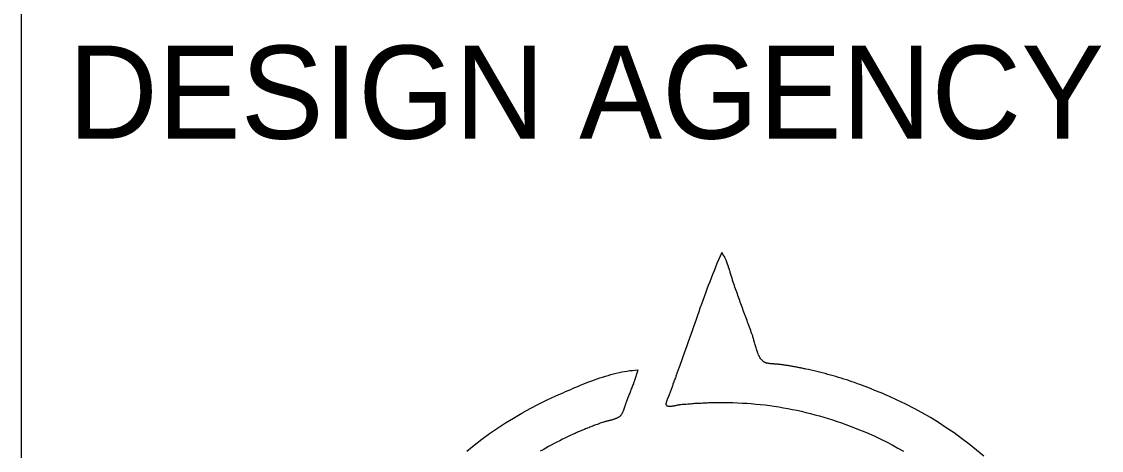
# Model space of a CAD drawing. Extents: x -0.7 to 34, y 0 to 22.
# Drawn here: x 32 to 33.162, y 4.015 to 4.476 of the extents above; entities that cross this region are included whole.
import ezdxf

# ---------------------------------------------------------------- set-up
doc = ezdxf.new("R2010")
doc.units = 0
doc.layers.add('SH_Border', color=7, linetype='Continuous')
doc.layers.add('SH_Text', color=7, linetype='Continuous')

msp = doc.modelspace()

# ---------------------------------------------------------------- linework, layer by layer
at = {"layer": 'SH_Border'}
msp.add_line((32, 0.5), (32, 21.5), dxfattribs=at)
at = {"layer": 'SH_Text'}
for points in [[(32.7532, 4.2277), (32.7515, 4.2238), (32.7498, 4.2199), (32.7481, 4.216), (32.7466, 4.212), (32.745, 4.208), (32.7434, 4.2041), (32.7418, 4.2001), (32.7403, 4.1961), (32.7387, 4.1921), (32.7372, 4.1881), (32.7357, 4.1841), (32.7342, 4.1801), (32.7328, 4.176), (32.7313, 4.172), (32.7298, 4.168), (32.7284, 4.1639), (32.7271, 4.1599), (32.7256, 4.1558), (32.7241, 4.1518), (32.7227, 4.1478), (32.7214, 4.1436), (32.7199, 4.1396), (32.7184, 4.1355), (32.7171, 4.1315), (32.7157, 4.1275), (32.7142, 4.1235), (32.7129, 4.1194), (32.7114, 4.1154), (32.71, 4.1114), (32.7085, 4.1074), (32.707, 4.1035)], [(32.7656, 4.1959), (32.7652, 4.1969), (32.7649, 4.1978), (32.7646, 4.1988), (32.7643, 4.1998), (32.764, 4.2009), (32.7637, 4.202), (32.7633, 4.2031), (32.7631, 4.2041), (32.7627, 4.2051), (32.7623, 4.2063), (32.7621, 4.2074), (32.7617, 4.2085), (32.7614, 4.2096), (32.761, 4.2107), (32.7606, 4.2118), (32.7603, 4.2129), (32.7599, 4.214), (32.7595, 4.2151), (32.7592, 4.2161), (32.7587, 4.2172), (32.7583, 4.2182), (32.7578, 4.2193), (32.7575, 4.2203), (32.757, 4.2214), (32.7565, 4.2223), (32.756, 4.2233), (32.7555, 4.2242), (32.7549, 4.2251), (32.7545, 4.226), (32.7538, 4.2268), (32.7532, 4.2277)], [(32.7856, 4.1404), (32.785, 4.1422), (32.7844, 4.144), (32.7837, 4.1457), (32.7831, 4.1475), (32.7823, 4.1493), (32.7817, 4.1512), (32.781, 4.1529), (32.7804, 4.1547), (32.7797, 4.1565), (32.7791, 4.1582), (32.7783, 4.16), (32.7777, 4.1618), (32.777, 4.1637), (32.7764, 4.1654), (32.7758, 4.1672), (32.7751, 4.169), (32.7745, 4.1708), (32.7739, 4.1725), (32.7731, 4.1743), (32.7725, 4.1761), (32.7719, 4.178), (32.7712, 4.1797), (32.7706, 4.1815), (32.77, 4.1833), (32.7694, 4.1851), (32.7686, 4.1869), (32.768, 4.1886), (32.7674, 4.1904), (32.7668, 4.1923), (32.7662, 4.1941), (32.7656, 4.1959)], [(32.7979, 4.1106), (32.7973, 4.1112), (32.7966, 4.1118), (32.796, 4.1124), (32.7954, 4.1131), (32.7949, 4.1138), (32.7943, 4.1147), (32.7939, 4.1156), (32.7934, 4.1165), (32.7929, 4.1175), (32.7925, 4.1186), (32.792, 4.1195), (32.7917, 4.1206), (32.7913, 4.1217), (32.7908, 4.1228), (32.7905, 4.1239), (32.7901, 4.1251), (32.7899, 4.1262), (32.7895, 4.1274), (32.7891, 4.1285), (32.7889, 4.1296), (32.7885, 4.1308), (32.7882, 4.1319), (32.7879, 4.133), (32.7877, 4.1341), (32.7873, 4.135), (32.7871, 4.136), (32.7868, 4.137), (32.7865, 4.138), (32.7862, 4.1388), (32.786, 4.1396), (32.7856, 4.1404)], [(32.5747, 4.0736), (32.5772, 4.0747), (32.5799, 4.0759), (32.5825, 4.077), (32.5852, 4.0782), (32.5879, 4.0794), (32.5907, 4.0806), (32.5934, 4.0818), (32.5962, 4.0829), (32.599, 4.0841), (32.6018, 4.0853), (32.6047, 4.0864), (32.6075, 4.0876), (32.6104, 4.0887), (32.6133, 4.0898), (32.6162, 4.0909), (32.6192, 4.0919), (32.6221, 4.093), (32.6251, 4.0938), (32.628, 4.0948), (32.6309, 4.0956), (32.6338, 4.0965), (32.6369, 4.0973), (32.6398, 4.0981), (32.6427, 4.0987), (32.6456, 4.0993), (32.6485, 4.0998), (32.6514, 4.1002), (32.6543, 4.1007), (32.6572, 4.101), (32.6601, 4.1012), (32.6629, 4.1015)], [(32.6629, 4.1015), (32.6626, 4.1002), (32.6623, 4.0992), (32.6619, 4.0979), (32.6616, 4.0969), (32.6612, 4.0958), (32.6609, 4.0945), (32.6605, 4.0935), (32.6601, 4.0922), (32.6596, 4.0912), (32.6593, 4.0901), (32.6589, 4.0888), (32.6584, 4.0878), (32.6581, 4.0867), (32.6576, 4.0856), (32.6572, 4.0844), (32.6567, 4.0833), (32.6564, 4.0822), (32.6559, 4.0811), (32.6555, 4.0799), (32.655, 4.0788), (32.6546, 4.0777), (32.6542, 4.0766), (32.6537, 4.0754), (32.6532, 4.0743), (32.6529, 4.0732), (32.6524, 4.0721), (32.652, 4.071), (32.6515, 4.0698), (32.6512, 4.0687), (32.6507, 4.0676), (32.6503, 4.0665)], [(32.707, 4.1035), (32.7067, 4.1025), (32.7063, 4.1016), (32.7061, 4.1006), (32.7057, 4.0996), (32.7054, 4.0987), (32.705, 4.0977), (32.7046, 4.0967), (32.7043, 4.0958), (32.7039, 4.0948), (32.7037, 4.0938), (32.7033, 4.0928), (32.7029, 4.092), (32.7026, 4.091), (32.7022, 4.0901), (32.7018, 4.0891), (32.7015, 4.0881), (32.7011, 4.0872), (32.7007, 4.0862), (32.7005, 4.0852), (32.7001, 4.0842), (32.6998, 4.0833), (32.6994, 4.0823), (32.699, 4.0813), (32.6987, 4.0804), (32.6983, 4.0795), (32.698, 4.0785), (32.6976, 4.0776), (32.6972, 4.0766), (32.6969, 4.0756), (32.6965, 4.0747), (32.6963, 4.0737)], [(32.8139, 4.1075), (32.8134, 4.1075), (32.8129, 4.1076), (32.8124, 4.1076), (32.8119, 4.1076), (32.8114, 4.1078), (32.8108, 4.1078), (32.8103, 4.1078), (32.8097, 4.1078), (32.8093, 4.1079), (32.8086, 4.1079), (32.808, 4.1079), (32.8076, 4.1079), (32.807, 4.108), (32.8063, 4.108), (32.8059, 4.1081), (32.8053, 4.1081), (32.8046, 4.1082), (32.8042, 4.1082), (32.8036, 4.1084), (32.8031, 4.1085), (32.8025, 4.1086), (32.802, 4.1087), (32.8015, 4.1089), (32.8009, 4.109), (32.8004, 4.1092), (32.7999, 4.1093), (32.7996, 4.1096), (32.7991, 4.1098), (32.7986, 4.1101), (32.7982, 4.1103), (32.7979, 4.1106)], [(32.8436, 4.1024), (32.8426, 4.1027), (32.8417, 4.1028), (32.8408, 4.103), (32.8398, 4.1033), (32.8388, 4.1034), (32.8379, 4.1036), (32.8369, 4.1038), (32.8359, 4.104), (32.835, 4.1041), (32.8341, 4.1044), (32.8331, 4.1045), (32.8322, 4.1047), (32.8312, 4.1049), (32.8302, 4.1051), (32.8293, 4.1052), (32.8283, 4.1055), (32.8273, 4.1056), (32.8263, 4.1057), (32.8254, 4.1059), (32.8244, 4.1061), (32.8234, 4.1062), (32.8225, 4.1063), (32.8215, 4.1065), (32.8205, 4.1067), (32.8196, 4.1068), (32.8186, 4.1069), (32.8177, 4.107), (32.8168, 4.1072), (32.8158, 4.1073), (32.8148, 4.1074), (32.8139, 4.1075)], [(32.9329, 4.0732), (32.9301, 4.0744), (32.9273, 4.0756), (32.9246, 4.0768), (32.9216, 4.0781), (32.9189, 4.0791), (32.9161, 4.0802), (32.9133, 4.0815), (32.9104, 4.0825), (32.9076, 4.0835), (32.9048, 4.0846), (32.9019, 4.0857), (32.8991, 4.0867), (32.8962, 4.0878), (32.8933, 4.0887), (32.8905, 4.0897), (32.8876, 4.0907), (32.8847, 4.0915), (32.8818, 4.0925), (32.8788, 4.0933), (32.8759, 4.0943), (32.873, 4.0952), (32.8701, 4.096), (32.8672, 4.0967), (32.8643, 4.0976), (32.8614, 4.0983), (32.8584, 4.099), (32.8554, 4.0998), (32.8525, 4.1005), (32.8495, 4.1012), (32.8466, 4.1018), (32.8436, 4.1024)], [(32.4788, 4.0143), (32.4868, 4.0207), (32.495, 4.0269), (32.5034, 4.033), (32.5119, 4.0388), (32.5205, 4.0445), (32.5292, 4.0498), (32.538, 4.055), (32.547, 4.06), (32.5561, 4.0647), (32.5653, 4.0693), (32.5747, 4.0736)], [(32.6503, 4.0665), (32.6501, 4.0661), (32.6499, 4.0656), (32.6498, 4.0652), (32.6496, 4.0647), (32.6495, 4.0642), (32.6493, 4.0638), (32.6492, 4.0631), (32.649, 4.0627), (32.6489, 4.0622), (32.6487, 4.0617), (32.6485, 4.0611), (32.6484, 4.0606), (32.6481, 4.0601), (32.648, 4.0595), (32.6478, 4.059), (32.6476, 4.0585), (32.6474, 4.0579), (32.6473, 4.0574), (32.647, 4.057), (32.6468, 4.0565), (32.6466, 4.056), (32.6463, 4.0555), (32.6461, 4.055), (32.6458, 4.0545), (32.6456, 4.0542), (32.6453, 4.0537), (32.6451, 4.0533), (32.6447, 4.053), (32.6445, 4.0525), (32.6441, 4.0521), (32.6438, 4.0519)], [(32.6963, 4.0737), (32.6961, 4.0735), (32.696, 4.0732), (32.6959, 4.073), (32.6958, 4.0727), (32.6957, 4.0724), (32.6955, 4.0721), (32.6954, 4.0718), (32.6952, 4.0714), (32.695, 4.071), (32.6949, 4.0707), (32.6947, 4.0703), (32.6946, 4.0699), (32.6944, 4.0696), (32.6942, 4.0691), (32.6941, 4.0687), (32.694, 4.0684), (32.6938, 4.068), (32.6937, 4.0675), (32.6936, 4.0671), (32.6935, 4.0668), (32.6935, 4.0664), (32.6933, 4.0661), (32.6933, 4.0657), (32.6932, 4.0653), (32.6932, 4.065), (32.6932, 4.0647), (32.6933, 4.0644), (32.6933, 4.0641), (32.6935, 4.0639), (32.6936, 4.0636), (32.6937, 4.0634)], [(32.7091, 4.0644), (32.7106, 4.0645), (32.7121, 4.0646), (32.7136, 4.0647), (32.7151, 4.0648), (32.7166, 4.065), (32.7181, 4.0651), (32.7195, 4.0652), (32.721, 4.0653), (32.7226, 4.0654), (32.724, 4.0656), (32.7255, 4.0657), (32.7269, 4.0657), (32.7285, 4.0658), (32.73, 4.0659), (32.7314, 4.0659), (32.7329, 4.0661), (32.7344, 4.0661), (32.7359, 4.0662), (32.7374, 4.0662), (32.7388, 4.0663), (32.7404, 4.0663), (32.7418, 4.0663), (32.7433, 4.0664), (32.7449, 4.0664), (32.7463, 4.0664), (32.7478, 4.0664), (32.7494, 4.0665), (32.7508, 4.0665), (32.7523, 4.0665), (32.7538, 4.0665), (32.7553, 4.0665)], [(32.7553, 4.0665), (32.7603, 4.0665), (32.7652, 4.0664), (32.7702, 4.0662), (32.7752, 4.0659), (32.7802, 4.0657), (32.785, 4.0653), (32.79, 4.0648), (32.7949, 4.0644), (32.7999, 4.0638), (32.8048, 4.0631), (32.8097, 4.0624), (32.8146, 4.0617), (32.8196, 4.0608), (32.8244, 4.06), (32.8293, 4.059), (32.8341, 4.0581), (32.839, 4.057), (32.8438, 4.0558), (32.8487, 4.0547), (32.8534, 4.0533), (32.8582, 4.052), (32.863, 4.0507), (32.8678, 4.0492), (32.8725, 4.0477), (32.8773, 4.0462), (32.882, 4.0446), (32.8866, 4.0429), (32.8913, 4.0412), (32.8959, 4.0394), (32.9005, 4.0376), (32.9052, 4.0357)], [(33.0351, 4.0088), (33.0272, 4.0154), (33.0194, 4.0217), (33.0112, 4.0277), (33.0031, 4.0337), (32.9947, 4.0394), (32.9863, 4.045), (32.9777, 4.0503), (32.9689, 4.0553), (32.9601, 4.0601), (32.9511, 4.0647), (32.942, 4.0691), (32.9329, 4.0732)], [(32.6937, 4.0634), (32.694, 4.0633), (32.6942, 4.063), (32.6946, 4.0629), (32.6949, 4.0628), (32.6954, 4.0627), (32.6958, 4.0627), (32.6963, 4.0625), (32.6967, 4.0625), (32.6973, 4.0625), (32.6978, 4.0625), (32.6984, 4.0625), (32.699, 4.0627), (32.6997, 4.0627), (32.7003, 4.0628), (32.7009, 4.0629), (32.7015, 4.063), (32.7021, 4.063), (32.7027, 4.0631), (32.7033, 4.0633), (32.7039, 4.0634), (32.7045, 4.0635), (32.705, 4.0636), (32.7056, 4.0638), (32.7062, 4.0639), (32.7067, 4.064), (32.7072, 4.0641), (32.7077, 4.0641), (32.708, 4.0642), (32.7085, 4.0644), (32.7087, 4.0644), (32.7091, 4.0644)], [(32.6259, 4.0453), (32.6248, 4.045), (32.6236, 4.0445), (32.6225, 4.0441), (32.6213, 4.0437), (32.6202, 4.0433), (32.6192, 4.0429), (32.6179, 4.0425), (32.6168, 4.0421), (32.6156, 4.0417), (32.6145, 4.0412), (32.6135, 4.0407), (32.6122, 4.0404), (32.6111, 4.0399), (32.6101, 4.0394), (32.6088, 4.039), (32.6078, 4.0385), (32.6067, 4.038), (32.6055, 4.0376), (32.6044, 4.0372), (32.6033, 4.0367), (32.6022, 4.0362), (32.601, 4.0357), (32.5999, 4.0353), (32.5988, 4.0348), (32.5977, 4.0343), (32.5966, 4.0338), (32.5955, 4.0333), (32.5944, 4.0328), (32.5932, 4.0324), (32.5921, 4.0317), (32.591, 4.0313)], [(32.6438, 4.0519), (32.6434, 4.0515), (32.6429, 4.0511), (32.6424, 4.0508), (32.6421, 4.0505), (32.6415, 4.0502), (32.641, 4.0499), (32.6405, 4.0497), (32.6399, 4.0493), (32.6393, 4.0491), (32.6387, 4.0488), (32.6381, 4.0487), (32.6375, 4.0485), (32.6369, 4.0482), (32.6362, 4.0481), (32.6356, 4.0479), (32.635, 4.0476), (32.6343, 4.0475), (32.6337, 4.0474), (32.6331, 4.0471), (32.6324, 4.047), (32.6318, 4.0469), (32.6312, 4.0467), (32.6305, 4.0465), (32.6299, 4.0464), (32.6293, 4.0463), (32.6287, 4.0461), (32.6281, 4.0459), (32.6275, 4.0458), (32.627, 4.0456), (32.6264, 4.0454), (32.6259, 4.0453)], [(32.591, 4.0313), (32.588, 4.0299), (32.585, 4.0284), (32.5819, 4.0269), (32.5789, 4.0254), (32.5759, 4.0239), (32.5728, 4.0223), (32.5698, 4.0207), (32.5669, 4.0191), (32.5639, 4.0174), (32.561, 4.0157), (32.558, 4.014)], [(32.9052, 4.0357), (32.9116, 4.033), (32.9179, 4.0302), (32.9242, 4.0271), (32.9305, 4.0241), (32.9367, 4.0208), (32.9427, 4.0174), (32.9488, 4.014)]]:
    msp.add_lwpolyline(points, dxfattribs=at)

# ---------------------------------------------------------------- texts
msp.add_text('DESIGN AGENCY', height=0.1, dxfattribs=at).set_placement((32.05, 4.35))

doc.saveas('drawing.dxf')
